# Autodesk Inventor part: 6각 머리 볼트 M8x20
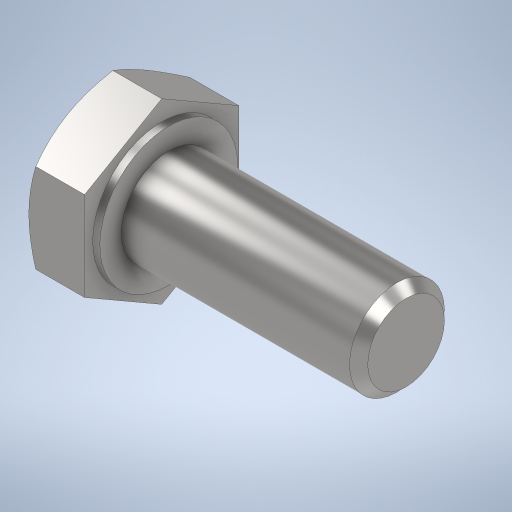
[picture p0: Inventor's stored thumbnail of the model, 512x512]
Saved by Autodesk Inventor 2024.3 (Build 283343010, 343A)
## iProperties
Created: 2025-11
Part Number: 6각 머리 볼트 M8x20
Material: 강철, 연강
Description: 6각 머리 볼트 및 6각 머리 나사
Document SubType Name: Modeling
Designer: PC2-15
Density: 7.85 g/cm^3
Appearance: 기본값
Author: jhkim
Sending System: Autodesk Inventor 2026
Preprocessor: ST-DEVELOPER v20.1
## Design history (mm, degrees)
node "6각 머리 볼트 M8x201"
node "솔리드1"
body "Solid1"
